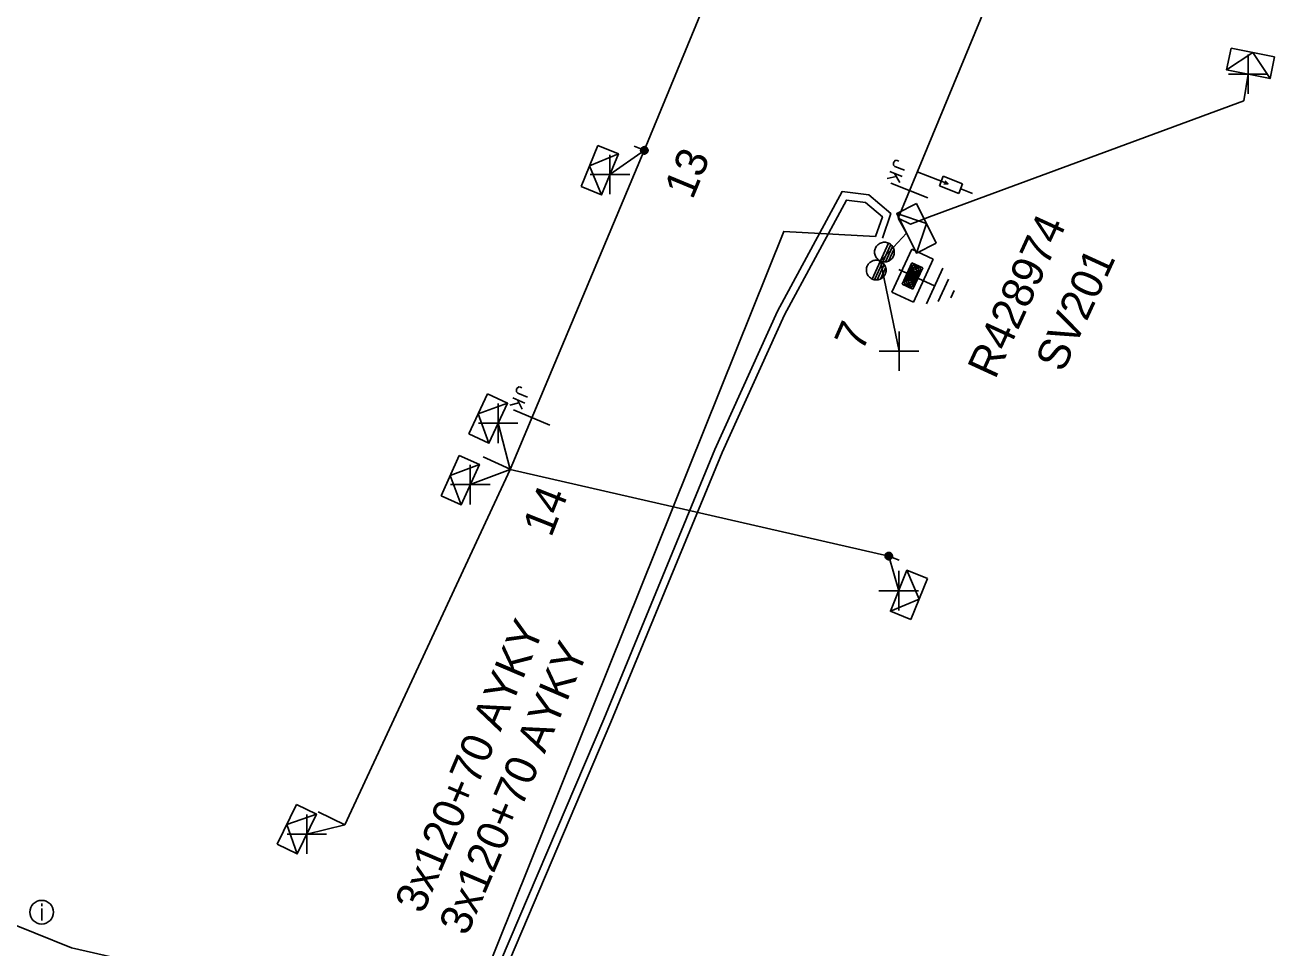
# Model space of a CAD drawing. Extents: x -540466 to -537383, y -1184038 to -1179972.
# Drawn here: x -537733.89 to -537694.26, y -1180525.39 to -1180496.15 of the extents above; entities that cross this region are included whole.
import ezdxf

# ---------------------------------------------------------------- set-up
doc = ezdxf.new("R2010")
doc.units = 0
for name, color, linetype in [('Vrstva 1', 7, 'Continuous'), ('Vrstva 10', 7, 'Continuous'), ('Vrstva 13', 7, 'Continuous'), ('Vrstva 14', 7, 'Continuous'), ('Vrstva 15', 7, 'Continuous'), ('Vrstva 16', 7, 'Continuous'), ('Vrstva 18', 7, 'Continuous'), ('Vrstva 2', 7, 'Continuous'), ('Vrstva 28', 7, 'Continuous'), ('Vrstva 29', 7, 'Continuous'), ('Vrstva 30', 7, 'Continuous'), ('Vrstva 31', 7, 'Continuous'), ('Vrstva 34', 7, 'Continuous'), ('Vrstva 36', 7, 'Continuous'), ('Vrstva 4', 7, 'Continuous'), ('Vrstva 5', 7, 'Continuous'), ('Vrstva 50', 7, 'Continuous'), ('Vrstva 52', 7, 'Continuous'), ('Vrstva 54', 7, 'Continuous'), ('Vrstva 6', 7, 'Continuous'), ('Vrstva 8', 7, 'Continuous'), ('Vrstva 9', 7, 'Continuous')]:
    doc.layers.add(name, color=color, linetype=linetype)

# ---------------------------------------------------------------- blocks, each defined once
blk = doc.blocks.new('NN450')
at = {"layer": 'Vrstva 2'}
for points in [[(0, 0), (-0.003, 0.065), (-0.013, 0.13), (-0.031, 0.193), (-0.054, 0.254), (-0.084, 0.312), (-0.119, 0.367), (-0.161, 0.418), (-0.207, 0.464), (-0.258, 0.505), (-0.313, 0.541), (-0.371, 0.571), (-0.432, 0.594), (-0.495, 0.611), (-0.559, 0.621), (-0.625, 0.625), (-0.69, 0.621), (-0.755, 0.611), (-0.818, 0.594), (-0.879, 0.571), (-0.938, 0.541), (-0.992, 0.505), (-1.043, 0.464), (-1.089, 0.418), (-1.13, 0.367), (-1.166, 0.312), (-1.196, 0.254), (-1.219, 0.193), (-1.236, 0.13), (-1.246, 0.065), (-1.25, 0), (-1.246, -0.066), (-1.236, -0.13), (-1.219, -0.193), (-1.196, -0.255), (-1.166, -0.313), (-1.13, -0.368), (-1.089, -0.419), (-1.043, -0.465), (-0.992, -0.506), (-0.937, -0.542), (-0.879, -0.571), (-0.818, -0.595), (-0.755, -0.612), (-0.69, -0.622), (-0.625, -0.625), (-0.559, -0.622), (-0.495, -0.612), (-0.432, -0.595), (-0.37, -0.571), (-0.312, -0.542), (-0.258, -0.506), (-0.207, -0.465), (-0.161, -0.419), (-0.119, -0.368), (-0.084, -0.313), (-0.054, -0.254), (-0.031, -0.193), (-0.013, -0.13), (-0.003, -0.066), (0, 0)], [(1.25, 0), (1.247, 0.065), (1.237, 0.13), (1.219, 0.193), (1.196, 0.254), (1.166, 0.312), (1.131, 0.367), (1.089, 0.418), (1.043, 0.464), (0.992, 0.505), (0.937, 0.541), (0.879, 0.571), (0.818, 0.594), (0.755, 0.611), (0.691, 0.621), (0.625, 0.625), (0.56, 0.621), (0.495, 0.611), (0.432, 0.594), (0.371, 0.571), (0.312, 0.541), (0.258, 0.505), (0.207, 0.464), (0.161, 0.418), (0.12, 0.367), (0.084, 0.312), (0.054, 0.254), (0.031, 0.193), (0.014, 0.13), (0.004, 0.065), (0, 0), (0.004, -0.066), (0.014, -0.13), (0.031, -0.193), (0.054, -0.255), (0.084, -0.313), (0.12, -0.368), (0.161, -0.419), (0.207, -0.465), (0.258, -0.506), (0.313, -0.542), (0.371, -0.571), (0.432, -0.595), (0.495, -0.612), (0.56, -0.622), (0.625, -0.625), (0.691, -0.622), (0.755, -0.612), (0.818, -0.595), (0.88, -0.571), (0.938, -0.542), (0.992, -0.506), (1.043, -0.465), (1.089, -0.419), (1.131, -0.368), (1.166, -0.313), (1.196, -0.254), (1.219, -0.193), (1.237, -0.13), (1.247, -0.066), (1.25, 0)], [(-1.25, 0), (1.25, 0)], [(-1.23, -0.158), (-0.02, -0.158)], [(-1.161, -0.315), (-0.088, -0.315)], [(-1.033, -0.473), (-0.216, -0.473)], [(0.02, -0.158), (1.23, -0.158)], [(0.089, -0.315), (1.162, -0.315)], [(0.217, -0.473), (1.034, -0.473)]]:
    blk.add_lwpolyline(points, dxfattribs=at)
blk = doc.blocks.new('NN840')
at = {"layer": 'Vrstva 15'}
for points in [[(0.003, 0.619), (0.003, -0.631)], [(-0.538, -0.385), (-0.538, -0.71)], [(-0.332, -0.385), (-0.332, -0.798)], [(-0.332, -0.641), (-0.125, -0.385)], [(-0.745, -0.71), (-0.745, -0.66)], [(-0.73, -0.764), (-0.745, -0.71)], [(-0.657, -0.798), (-0.73, -0.764)], [(-0.558, -0.764), (-0.627, -0.798)], [(-0.538, -0.71), (-0.558, -0.764)], [(-0.263, -0.557), (-0.091, -0.798)], [(-0.627, -0.798), (-0.657, -0.798)]]:
    blk.add_lwpolyline(points, dxfattribs=at)
blk = doc.blocks.new('NN770')
at = {"layer": 'Vrstva 10'}
for p, q in [((0.002, 0.187), (0.002, 0.263)), ((0.002, -0.276), (0.002, 0.111))]:
    blk.add_line(p, q, dxfattribs=at)
blk.add_circle((0, -0.008), 0.375, dxfattribs=at)
blk = doc.blocks.new('NN800')
at = {"layer": 'Vrstva 1'}
for points in [[(-0.442, 0.442), (0.442, -0.442)], [(-0.442, -0.442), (0.442, 0.442)]]:
    blk.add_lwpolyline(points, dxfattribs=at)
blk = doc.blocks.new('NN820')
at = {"layer": 'Vrstva 13'}
for points in [[(-0.003, 0.004), (-0.003, -1.049)], [(-0.165, -0.813), (0.165, -0.813)], [(-0.165, -1.473), (-0.165, -0.813)], [(-0.003, -1.049), (-0.062, -0.926)], [(-0.003, -1.049), (0.057, -0.926)], [(0.165, -0.813), (0.165, -1.473)], [(0.165, -1.473), (-0.165, -1.473)], [(-0.003, -1.473), (-0.003, -1.871)]]:
    blk.add_lwpolyline(points, dxfattribs=at)
blk = doc.blocks.new('NN620')
at = {"layer": 'Vrstva 8'}
for points in [[(0.752, 0.004), (-0.748, 0.004)], [(-0.748, 0.004), (-0.748, -0.746)], [(0.752, -0.746), (0.752, 0.004)], [(0.368, -0.18), (-0.376, -0.18)], [(-0.376, -0.18), (-0.376, -0.558)], [(0.321, -0.227), (-0.329, -0.227)], [(-0.329, -0.227), (-0.329, -0.51)], [(0.274, -0.274), (-0.281, -0.274)], [(-0.281, -0.274), (-0.281, -0.463)], [(0.227, -0.321), (-0.234, -0.321)], [(-0.234, -0.321), (-0.234, -0.416)], [(-0.193, -0.369), (0.185, -0.369)], [(0.227, -0.416), (0.227, -0.321)], [(0.274, -0.463), (0.274, -0.274)], [(0.321, -0.51), (0.321, -0.227)], [(0.368, -0.558), (0.368, -0.18)], [(-0.748, -0.746), (0.752, -0.746)], [(-0.376, -0.558), (0.368, -0.558)], [(-0.329, -0.51), (0.321, -0.51)], [(-0.281, -0.463), (0.274, -0.463)], [(-0.234, -0.416), (0.227, -0.416)]]:
    blk.add_lwpolyline(points, dxfattribs=at)
blk = doc.blocks.new('NN630')
at = {"layer": 'Vrstva 9'}
for points in [[(-0.003, -0.7), (-0.703, 0)], [(-0.703, -0.7), (-0.703, 0), (0.697, 0), (0.697, -0.7)], [(-0.003, -0.7), (0.697, 0)], [(-0.703, -0.7), (0.697, -0.7)]]:
    blk.add_lwpolyline(points, dxfattribs=at)
blk = doc.blocks.new('NN810')
at = {"layer": 'Vrstva 14'}
for points in [[(0.004, -0.64), (0.004, -1.89)], [(0.629, -1.89), (-0.621, -1.89)], [(0.388, -2.2), (-0.399, -2.2)], [(0.004, -2.515), (-0.124, -2.515)], [(0.137, -2.515), (0.004, -2.515)]]:
    blk.add_lwpolyline(points, dxfattribs=at)
blk = doc.blocks.new('NN500')
at = {"layer": 'Vrstva 2'}
for points in [[(-0.001, -0.235), (0.023, -0.234), (0.048, -0.23), (0.071, -0.224), (0.094, -0.215), (0.116, -0.204), (0.137, -0.191), (0.156, -0.175), (0.173, -0.158), (0.189, -0.139), (0.202, -0.118), (0.213, -0.096), (0.222, -0.073), (0.229, -0.049), (0.232, -0.025), (0.234, 0), (0.232, 0.024), (0.229, 0.048), (0.222, 0.072), (0.213, 0.095), (0.202, 0.117), (0.189, 0.138), (0.173, 0.157), (0.156, 0.174), (0.137, 0.19), (0.116, 0.203), (0.094, 0.214), (0.071, 0.223), (0.048, 0.229), (0.023, 0.233), (-0.001, 0.235), (-0.026, 0.233), (-0.05, 0.229), (-0.074, 0.223), (-0.097, 0.214), (-0.119, 0.203), (-0.139, 0.19), (-0.158, 0.174), (-0.176, 0.157), (-0.191, 0.138), (-0.205, 0.117), (-0.216, 0.095), (-0.225, 0.072), (-0.231, 0.048), (-0.235, 0.024), (-0.236, 0), (-0.235, -0.025), (-0.231, -0.049), (-0.225, -0.073), (-0.216, -0.096), (-0.205, -0.118), (-0.191, -0.139), (-0.176, -0.158), (-0.158, -0.175), (-0.139, -0.191), (-0.119, -0.204), (-0.097, -0.215), (-0.074, -0.224), (-0.05, -0.23), (-0.026, -0.234), (-0.001, -0.235)], [(-0.001, -0.235), (0.023, -0.234), (0.048, -0.23), (0.071, -0.224), (0.094, -0.215), (0.116, -0.204), (0.137, -0.191), (0.156, -0.175), (0.173, -0.158), (0.189, -0.139), (0.202, -0.118), (0.213, -0.096), (0.222, -0.073), (0.229, -0.049), (0.232, -0.025), (0.234, 0), (0.232, 0.024), (0.229, 0.048), (0.222, 0.072), (0.213, 0.095), (0.202, 0.117), (0.189, 0.138), (0.173, 0.157), (0.156, 0.174), (0.137, 0.19), (0.116, 0.203), (0.094, 0.214), (0.071, 0.223), (0.048, 0.229), (0.023, 0.233), (-0.001, 0.235), (-0.026, 0.233), (-0.05, 0.229), (-0.074, 0.223), (-0.097, 0.214), (-0.119, 0.203), (-0.139, 0.19), (-0.158, 0.174), (-0.176, 0.157), (-0.191, 0.138), (-0.205, 0.117), (-0.216, 0.095), (-0.225, 0.072), (-0.231, 0.048), (-0.235, 0.024), (-0.236, 0), (-0.235, -0.025), (-0.231, -0.049), (-0.225, -0.073), (-0.216, -0.096), (-0.205, -0.118), (-0.191, -0.139), (-0.176, -0.158), (-0.158, -0.175), (-0.139, -0.191), (-0.119, -0.204), (-0.097, -0.215), (-0.074, -0.224), (-0.05, -0.23), (-0.026, -0.234), (-0.001, -0.235)], [(-0.001, -0.206), (0.02, -0.205), (0.041, -0.201), (0.062, -0.196), (0.082, -0.188), (0.101, -0.178), (0.12, -0.167), (0.136, -0.153), (0.151, -0.138), (0.165, -0.121), (0.177, -0.103), (0.186, -0.084), (0.194, -0.064), (0.2, -0.043), (0.203, -0.022), (0.204, 0), (0.203, 0.021), (0.2, 0.042), (0.194, 0.063), (0.186, 0.083), (0.177, 0.102), (0.165, 0.12), (0.151, 0.137), (0.136, 0.152), (0.12, 0.166), (0.101, 0.177), (0.082, 0.187), (0.062, 0.195), (0.041, 0.2), (0.02, 0.204), (-0.001, 0.205), (-0.023, 0.204), (-0.044, 0.2), (-0.065, 0.195), (-0.085, 0.187), (-0.104, 0.177), (-0.122, 0.166), (-0.139, 0.152), (-0.154, 0.137), (-0.167, 0.12), (-0.179, 0.102), (-0.189, 0.083), (-0.197, 0.063), (-0.202, 0.042), (-0.205, 0.021), (-0.207, 0), (-0.205, -0.022), (-0.202, -0.043), (-0.197, -0.064), (-0.189, -0.084), (-0.179, -0.103), (-0.167, -0.121), (-0.154, -0.138), (-0.139, -0.153), (-0.122, -0.167), (-0.104, -0.178), (-0.085, -0.188), (-0.065, -0.196), (-0.044, -0.201), (-0.023, -0.205), (-0.001, -0.206)], [(-0.001, -0.176), (0.017, -0.175), (0.035, -0.172), (0.053, -0.168), (0.07, -0.161), (0.087, -0.153), (0.102, -0.143), (0.116, -0.131), (0.129, -0.118), (0.141, -0.104), (0.151, -0.088), (0.159, -0.072), (0.166, -0.055), (0.171, -0.037), (0.174, -0.019), (0.175, 0), (0.174, 0.018), (0.171, 0.036), (0.166, 0.054), (0.159, 0.071), (0.151, 0.087), (0.141, 0.103), (0.129, 0.117), (0.116, 0.13), (0.102, 0.142), (0.087, 0.152), (0.07, 0.16), (0.053, 0.167), (0.035, 0.172), (0.017, 0.174), (-0.001, 0.175), (-0.02, 0.174), (-0.038, 0.172), (-0.056, 0.167), (-0.073, 0.16), (-0.089, 0.152), (-0.105, 0.142), (-0.119, 0.13), (-0.132, 0.117), (-0.143, 0.103), (-0.153, 0.087), (-0.162, 0.071), (-0.168, 0.054), (-0.173, 0.036), (-0.176, 0.018), (-0.177, 0), (-0.176, -0.019), (-0.173, -0.037), (-0.168, -0.055), (-0.162, -0.072), (-0.153, -0.088), (-0.143, -0.104), (-0.132, -0.118), (-0.119, -0.131), (-0.105, -0.143), (-0.089, -0.153), (-0.073, -0.161), (-0.056, -0.168), (-0.038, -0.172), (-0.02, -0.175), (-0.001, -0.176)], [(-0.001, -0.147), (0.014, -0.146), (0.029, -0.143), (0.044, -0.139), (0.058, -0.134), (0.072, -0.127), (0.085, -0.119), (0.097, -0.109), (0.107, -0.098), (0.117, -0.086), (0.125, -0.073), (0.132, -0.06), (0.138, -0.046), (0.142, -0.031), (0.144, -0.016), (0.145, 0), (0.144, 0.015), (0.142, 0.03), (0.138, 0.045), (0.132, 0.059), (0.125, 0.073), (0.117, 0.086), (0.107, 0.097), (0.097, 0.108), (0.085, 0.118), (0.072, 0.126), (0.058, 0.133), (0.044, 0.139), (0.029, 0.143), (0.014, 0.145), (-0.001, 0.146), (-0.017, 0.145), (-0.032, 0.143), (-0.046, 0.139), (-0.061, 0.133), (-0.074, 0.126), (-0.087, 0.118), (-0.099, 0.108), (-0.11, 0.097), (-0.119, 0.086), (-0.128, 0.073), (-0.135, 0.059), (-0.14, 0.045), (-0.144, 0.03), (-0.147, 0.015), (-0.147, 0), (-0.147, -0.016), (-0.144, -0.031), (-0.14, -0.046), (-0.135, -0.06), (-0.128, -0.073), (-0.119, -0.086), (-0.11, -0.098), (-0.099, -0.109), (-0.087, -0.119), (-0.074, -0.127), (-0.061, -0.134), (-0.046, -0.139), (-0.032, -0.143), (-0.017, -0.146), (-0.001, -0.147)], [(-0.001, -0.117), (0.011, -0.116), (0.023, -0.114), (0.035, -0.111), (0.046, -0.107), (0.057, -0.101), (0.067, -0.095), (0.077, -0.087), (0.085, -0.078), (0.093, -0.069), (0.1, -0.059), (0.105, -0.048), (0.11, -0.036), (0.113, -0.025), (0.115, -0.013), (0.115, 0), (0.115, 0.012), (0.113, 0.024), (0.11, 0.036), (0.105, 0.047), (0.1, 0.058), (0.093, 0.068), (0.085, 0.078), (0.077, 0.086), (0.067, 0.094), (0.057, 0.101), (0.046, 0.106), (0.035, 0.11), (0.023, 0.114), (0.011, 0.116), (-0.001, 0.116), (-0.013, 0.116), (-0.025, 0.114), (-0.037, 0.11), (-0.049, 0.106), (-0.059, 0.101), (-0.07, 0.094), (-0.079, 0.086), (-0.088, 0.078), (-0.096, 0.068), (-0.102, 0.058), (-0.108, 0.047), (-0.112, 0.036), (-0.115, 0.024), (-0.117, 0.012), (-0.118, 0), (-0.117, -0.013), (-0.115, -0.025), (-0.112, -0.036), (-0.108, -0.048), (-0.102, -0.059), (-0.096, -0.069), (-0.088, -0.078), (-0.079, -0.087), (-0.07, -0.095), (-0.059, -0.101), (-0.049, -0.107), (-0.037, -0.111), (-0.025, -0.114), (-0.013, -0.116), (-0.001, -0.117)], [(-0.001, -0.087), (0.008, -0.087), (0.017, -0.085), (0.026, -0.083), (0.034, -0.08), (0.042, -0.076), (0.05, -0.071), (0.057, -0.065), (0.063, -0.059), (0.069, -0.051), (0.074, -0.044), (0.078, -0.036), (0.081, -0.027), (0.084, -0.019), (0.085, -0.01), (0.086, 0), (0.085, 0.009), (0.084, 0.018), (0.081, 0.026), (0.078, 0.035), (0.074, 0.043), (0.069, 0.051), (0.063, 0.058), (0.057, 0.064), (0.05, 0.07), (0.042, 0.075), (0.034, 0.079), (0.026, 0.082), (0.017, 0.085), (0.008, 0.086), (-0.001, 0.087), (-0.01, 0.086), (-0.019, 0.085), (-0.028, 0.082), (-0.037, 0.079), (-0.045, 0.075), (-0.052, 0.07), (-0.059, 0.064), (-0.066, 0.058), (-0.072, 0.051), (-0.077, 0.043), (-0.081, 0.035), (-0.084, 0.026), (-0.086, 0.018), (-0.088, 0.009), (-0.088, 0), (-0.088, -0.01), (-0.086, -0.019), (-0.084, -0.027), (-0.081, -0.036), (-0.077, -0.044), (-0.072, -0.052), (-0.066, -0.059), (-0.059, -0.065), (-0.052, -0.071), (-0.045, -0.076), (-0.037, -0.08), (-0.028, -0.083), (-0.019, -0.085), (-0.01, -0.087), (-0.001, -0.087)], [(-0.001, -0.058), (0.005, -0.057), (0.011, -0.056), (0.016, -0.055), (0.022, -0.053), (0.027, -0.05), (0.032, -0.047), (0.037, -0.043), (0.041, -0.039), (0.045, -0.034), (0.048, -0.029), (0.051, -0.024), (0.053, -0.018), (0.055, -0.012), (0.056, -0.006), (0.056, 0), (0.056, 0.006), (0.055, 0.011), (0.053, 0.017), (0.051, 0.023), (0.048, 0.028), (0.045, 0.033), (0.041, 0.038), (0.037, 0.042), (0.032, 0.046), (0.027, 0.049), (0.022, 0.052), (0.016, 0.054), (0.011, 0.056), (0.005, 0.057), (-0.001, 0.057), (-0.007, 0.057), (-0.013, 0.056), (-0.019, 0.054), (-0.025, 0.052), (-0.03, 0.049), (-0.035, 0.046), (-0.04, 0.042), (-0.044, 0.038), (-0.048, 0.033), (-0.051, 0.028), (-0.054, 0.023), (-0.056, 0.017), (-0.057, 0.011), (-0.058, 0.006), (-0.059, 0), (-0.058, -0.006), (-0.057, -0.012), (-0.056, -0.018), (-0.054, -0.024), (-0.051, -0.029), (-0.048, -0.034), (-0.044, -0.039), (-0.04, -0.043), (-0.035, -0.047), (-0.03, -0.05), (-0.025, -0.053), (-0.019, -0.055), (-0.013, -0.056), (-0.007, -0.057), (-0.001, -0.058)], [(-0.001, -0.028), (0.002, -0.028), (0.005, -0.028), (0.007, -0.027), (0.01, -0.026), (0.013, -0.024), (0.015, -0.023), (0.017, -0.021), (0.019, -0.019), (0.021, -0.017), (0.023, -0.014), (0.024, -0.012), (0.025, -0.009), (0.026, -0.006), (0.026, -0.003), (0.027, 0), (0.026, 0.002), (0.026, 0.005), (0.025, 0.008), (0.024, 0.011), (0.023, 0.013), (0.021, 0.016), (0.019, 0.018), (0.017, 0.02), (0.015, 0.022), (0.013, 0.024), (0.01, 0.025), (0.007, 0.026), (0.005, 0.027), (0.002, 0.027), (-0.001, 0.027), (-0.004, 0.027), (-0.007, 0.027), (-0.01, 0.026), (-0.012, 0.025), (-0.015, 0.024), (-0.018, 0.022), (-0.02, 0.02), (-0.022, 0.018), (-0.024, 0.016), (-0.025, 0.013), (-0.027, 0.011), (-0.028, 0.008), (-0.028, 0.005), (-0.029, 0.002), (-0.029, 0), (-0.029, -0.003), (-0.028, -0.006), (-0.028, -0.009), (-0.027, -0.012), (-0.025, -0.014), (-0.024, -0.017), (-0.022, -0.019), (-0.02, -0.021), (-0.018, -0.023), (-0.015, -0.024), (-0.012, -0.026), (-0.01, -0.027), (-0.007, -0.028), (-0.004, -0.028), (-0.001, -0.028)], [(0.234, 0), (0.704, 0)]]:
    blk.add_lwpolyline(points, dxfattribs=at)
blk = doc.blocks.new('NN510')
at = {"layer": 'Vrstva 2'}
blk.add_lwpolyline([(0.001, 0.002), (0.001, 0.939)], dxfattribs=at)

msp = doc.modelspace()

# ---------------------------------------------------------------- linework, layer by layer
at = {"layer": 'Vrstva 4'}
msp.add_lwpolyline([(-537718.536, -1180510.223), (-537706.55, -1180512.97), (-537706.235, -1180514.068)], dxfattribs=at)
at = {"layer": 'Vrstva 5'}
for points in [[(-537734.68, -1180524.19), (-537734.74, -1180524.45), (-537732.42, -1180525.38), (-537728.3, -1180526.32), (-537725.94, -1180526.78), (-537719.916, -1180528.443), (-537719.145, -1180526.532), (-537715.575, -1180518.142), (-537712.055, -1180509.59), (-537710.072, -1180505.214), (-537708.029, -1180501.425), (-537707.177, -1180501.531), (-537706.489, -1180502.117), (-537706.751, -1180502.897)], [(-537694.259, -1180538.2), (-537694.383, -1180538.509), (-537694.85, -1180538.67), (-537700.14, -1180535.98), (-537704.89, -1180534.15), (-537714.67, -1180530.95), (-537719.56, -1180529.24), (-537719.684, -1180528.537), (-537718.915, -1180526.628), (-537715.345, -1180518.238), (-537711.825, -1180509.69), (-537709.848, -1180505.326), (-537707.891, -1180501.695), (-537707.283, -1180501.769), (-537706.751, -1180502.223), (-537706.972, -1180502.847)]]:
    msp.add_lwpolyline(points, dxfattribs=at)
at = {"layer": 'Vrstva 50'}
for points in [[(-537695.509, -1180475.222), (-537708.786, -1180486.772), (-537714.289, -1180500.117), (-537718.536, -1180510.223)], [(-537706.255, -1180502.27), (-537705.642, -1180500.791), (-537695.184, -1180475.522)]]:
    msp.add_lwpolyline(points, dxfattribs=at)
at = {"layer": 'Vrstva 52'}
for points in [[(-537706.255, -1180502.27), (-537705.862, -1180502.457), (-537705.264, -1180502.227), (-537695.308, -1180498.547), (-537695.168, -1180497.706)], [(-537706.255, -1180502.27), (-537705.987, -1180502.739), (-537706.815, -1180503.624), (-537706.223, -1180506.478)], [(-537706.972, -1180502.847), (-537709.876, -1180502.687), (-537719.944, -1180527.767), (-537711.939, -1180530.834), (-537711.509, -1180530.148)]]:
    msp.add_lwpolyline(points, dxfattribs=at)
at = {"layer": 'Vrstva 54'}
for points in [[(-537714.289, -1180500.117), (-537715.376, -1180500.882)], [(-537718.536, -1180510.223), (-537718.913, -1180508.765)], [(-537718.536, -1180510.223), (-537719.799, -1180510.708)]]:
    msp.add_lwpolyline(points, dxfattribs=at)
at = {"layer": 'Vrstva 8'}
msp.add_lwpolyline([(-537718.536, -1180510.223), (-537723.775, -1180521.485), (-537724.975, -1180521.779)], dxfattribs=at)

# ---------------------------------------------------------------- block references
at = {"layer": 'Vrstva 13'}
for name, p, xscale, yscale, rotation in [('NN500', (-537714.289, -1180500.117), 0.5000000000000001, 0.5, 157.57999991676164), ('NN450', (-537706.816, -1180503.625), 0.5, 0.49999999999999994, 65.39917218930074), ('NN500', (-537706.55, -1180512.97), 0.49999999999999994, 0.5000000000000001, -21.98999987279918)]:
    msp.add_blockref(name, p, dxfattribs=dict(at, xscale=xscale, yscale=yscale, rotation=rotation))
for p, rotation in [((-537718.536, -1180510.224), 64.97272221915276), ((-537723.774, -1180521.486), 64.16566394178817)]:
    msp.add_blockref('NN510', p, dxfattribs=dict(at, rotation=rotation))
at = {"layer": 'Vrstva 15', "rotation": 65.19926120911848}
msp.add_blockref('NN810', (-537706.815, -1180503.624), dxfattribs=at)
at = {"layer": 'Vrstva 16', "rotation": 68.49706113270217}
msp.add_blockref('NN820', (-537705.642, -1180500.791), dxfattribs=at)
at = {"layer": 'Vrstva 18'}
for p, rotation in [((-537705.891, -1180501.39), -111.5029389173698), ((-537717.845, -1180508.578), -112.79435559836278)]:
    msp.add_blockref('NN840', p, dxfattribs=dict(at, rotation=rotation))
at = {"layer": 'Vrstva 28', "rotation": 65.32699999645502}
msp.add_blockref('NN620', (-537706.133, -1180503.937), dxfattribs=at)
at = {"layer": 'Vrstva 31'}
for p, rotation in [((-537695.168, -1180497.706), 168.68557226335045), ((-537715.376, -1180500.882), -112.42006109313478), ((-537705.987, -1180502.739), 116.28159717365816), ((-537718.913, -1180508.765), -115.02727778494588), ((-537719.799, -1180510.708), -114.1805888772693), ((-537706.235, -1180514.068), 68.01026113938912), ((-537724.975, -1180521.779), -115.83433617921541)]:
    msp.add_blockref('NN630', p, dxfattribs=dict(at, rotation=rotation))
at = {"layer": 'Vrstva 34'}
for p, rotation in [((-537695.168, -1180497.706), 44.99999995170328), ((-537715.376, -1180500.882), 45), ((-537706.223, -1180506.478), 45), ((-537718.913, -1180508.765), 44.99999995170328), ((-537719.799, -1180510.708), 45), ((-537706.235, -1180514.068), 45), ((-537724.975, -1180521.779), 45)]:
    msp.add_blockref('NN800', p, dxfattribs=dict(at, rotation=rotation))
at = {"layer": 'Vrstva 36'}
msp.add_blockref('NN770', (-537733.368, -1180524.245), dxfattribs=at)

# ---------------------------------------------------------------- texts
at = {"layer": 'Vrstva 14'}
for s, rotation, p in [('13', 67.484, (-537712.765, -1180501.706)), ('7', 66.193, (-537707.391, -1180506.524)), ('14', 68.448, (-537717.239, -1180512.406))]:
    msp.add_text(s, height=1, rotation=rotation, dxfattribs=at).set_placement(p)
at = {"layer": 'Vrstva 29'}
msp.add_text('R428974', height=1, rotation=65.327, dxfattribs=at).set_placement((-537703.182, -1180507.4))
at = {"layer": 'Vrstva 30'}
msp.add_text('SV201', height=1, rotation=65.327, dxfattribs=at).set_placement((-537701.033, -1180507.185))
at = {"layer": 'Vrstva 6'}
for p in [(-537721.302, -1180524.338), (-537719.905, -1180525.037)]:
    msp.add_text('3x120+70 AYKY', height=1, rotation=66.95, dxfattribs=at).set_placement(p)

doc.saveas('drawing.dxf')
